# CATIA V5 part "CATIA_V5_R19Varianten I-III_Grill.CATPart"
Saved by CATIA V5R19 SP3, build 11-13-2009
Part number: Part2
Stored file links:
  \\S050023F.sifi.daimlerchrysler.com\tharmen$\Data\My Documents\CATIA_V5_R19Varianten I-III_Grill.CATPart
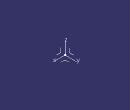
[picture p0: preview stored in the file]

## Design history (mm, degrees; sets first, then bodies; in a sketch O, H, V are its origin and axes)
AxisSystem1: origin (0, 0, 0), X (1, 0, 0), Y (0, 1, 0), Z (0, 0, 1)
Body1 "Grill" (main body)
  Sketch1 on yz-plane, origin (0, 0, 0), H (0, 1, 0), V (0, 0, 1)
    ellipse A1 centre (0, 0) semi-axes 100, 60 rotation 0
    point P1 (100, 0)
    point P2 (0, 60)
    line L1 (-86.6025, 30) -> (86.6025, 30)
    point P3 (-86.6025, 30)
    point P4 (86.6025, 30)
    line L2 (100, 0) -> (-100, 0)
    line L3 (86.6025, -30) -> (-86.6025, -30)
    point P6 (86.6025, -30)
    point P7 (-86.6025, -30)
    coincidence: P1 H, P2 V, A1 P1, A1 P2, P3 A1, P4 A1, P6 A1, P7 A1
    horizontal: L1 H, L2 H, L3 H
  Pad1: profile Sketch1, direction (1, 0, 0), length 20, thin wall 10
  Sketch2 on zx-plane, origin (0, 0, 0), H (-1, 0, 0), V (0, 0, 1)
    circle A1 centre (230, 0) radius 250
    point P2 (-20, 0)
    coincidence: A1 P2, P2 H
  Pocket1: profile Sketch2, direction (0, -1, 0), through (limit type 3), opposite side through (limit type 3), outer side
  Draft1: PullDir start face of Pad1, Angle -5, Neutral start face of Pad1
  Thickness1: Thickness 0, Face start face of Pad1
  Fillet1: radius 5, on edge [face of Pad1 | face of Pad1] (x12)
  Fillet2: radius 2, on face of Pocket1
Body2 "Shell"
  Solid1: linked copy from another document
  Shell1: IntOffset 1.5, Face face of Solid1, ExtOffset 0
Body3 "Variante I Aufmass 1.5mm"
  Solid2: linked copy from another document
  Thickness2: Thickness -1.5, Face face of Solid2
Body4 "Variante II Body.Ableitung, Close"
  Set1
    MultiExtract1: ListOfMultiExtractConstraints MultiExtractConstraint face of Shell1
  CloseSurface1: CloseElement MultiExtract1
Body5 "Variante II - remove"
  Solid3: linked copy from another document
  Body6 "Shell"
    Solid4: linked copy from another document
  Remove1: tool Body6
